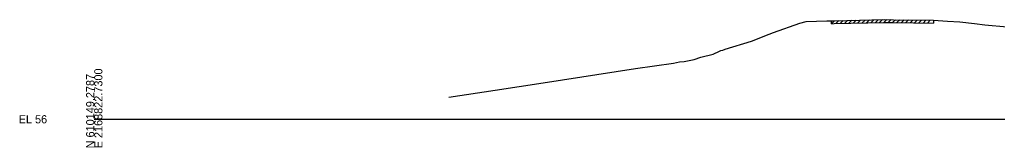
# Model space of a CAD drawing. Extents: x -26 to 6803, y -10 to 19606.
# Drawn here: x 1974.3 to 2310.6, y 12990.3 to 13034.3 of the extents above; entities that cross this region are included whole.
import ezdxf

# ---------------------------------------------------------------- set-up
doc = ezdxf.new("R2010")
doc.units = 0
for name, color, linetype in [('RD_GPK_XS_Cell', 7, 'Continuous'), ('RD_XS_ExGround', 7, 'Continuous'), ('RD_XS_ExPaveRet', 7, 'Continuous')]:
    doc.layers.add(name, color=color, linetype=linetype)

msp = doc.modelspace()

# ---------------------------------------------------------------- linework, layer by layer
at = {"layer": 'RD_GPK_XS_Cell'}
msp.add_line((2000, 13000), (2400, 13000), dxfattribs=at)
at = {"layer": 'RD_XS_ExGround'}
msp.add_lwpolyline([(2121.9, 13007.57), (2137.85, 13010.04), (2154.38, 13012.59), (2186.16, 13017.47), (2199.23, 13019.35), (2201.23, 13019.72), (2202.86, 13019.93), (2206.31, 13020.58), (2208.66, 13021.37), (2212.8, 13022.44), (2215.01, 13023.43), (2215.52, 13023.62), (2216.2, 13023.83), (2216.93, 13024.09), (2226.07, 13026.83), (2232.1, 13029.23), (2233.55, 13029.89), (2242.7, 13033.08), (2244.78, 13033.64), (2251.95, 13033.86), (2252.75, 13033.86), (2253.54, 13033.89), (2254.42, 13033.91), (2271.81, 13034.32), (2274.9, 13034.26), (2288.67, 13034.05), (2293.42, 13033.74), (2297.68, 13033.49), (2302.74, 13032.9), (2306.32, 13032.51), (2313.99, 13031.81)], dxfattribs=at)
at = {"layer": 'RD_XS_ExPaveRet'}
for p, q in [((2253.54, 13032.89), (2254.57, 13033.91)), ((2253.54, 13032.89), (2253.54, 13033.89)), ((2253.54, 13032.89), (2254.42, 13032.91)), ((2254.42, 13032.91), (2271.81, 13033.32)), ((2255.04, 13032.92), (2256.07, 13033.95)), ((2256.54, 13032.96), (2257.57, 13033.98)), ((2258.04, 13032.99), (2259.07, 13034.02)), ((2259.54, 13033.03), (2260.57, 13034.05)), ((2261.04, 13033.06), (2262.07, 13034.09)), ((2262.54, 13033.1), (2263.57, 13034.12)), ((2264.04, 13033.13), (2265.07, 13034.16)), ((2265.54, 13033.17), (2266.57, 13034.19)), ((2267.04, 13033.21), (2268.07, 13034.23)), ((2268.54, 13033.24), (2269.57, 13034.26)), ((2270.04, 13033.28), (2271.07, 13034.3)), ((2271.54, 13033.31), (2272.54, 13034.3)), ((2271.81, 13033.32), (2274.9, 13033.26)), ((2273.04, 13033.3), (2274.03, 13034.28)), ((2274.54, 13033.27), (2275.53, 13034.25)), ((2274.9, 13033.26), (2288.67, 13033.05)), ((2276.04, 13033.25), (2277.03, 13034.23)), ((2277.54, 13033.22), (2278.53, 13034.21)), ((2279.04, 13033.2), (2280.03, 13034.19)), ((2280.54, 13033.18), (2281.53, 13034.16)), ((2282.04, 13033.16), (2283.03, 13034.14)), ((2283.54, 13033.13), (2284.53, 13034.12)), ((2285.04, 13033.11), (2286.03, 13034.09)), ((2286.54, 13033.09), (2287.53, 13034.07)), ((2288.67, 13034.05), (2288.67, 13033.05)), ((2288.67, 13033.05), (2288.67, 13033.05))]:
    msp.add_line(p, q, dxfattribs=at)

# ---------------------------------------------------------------- texts
at = {"layer": 'RD_GPK_XS_Cell'}
for s, p in [('N 610149.2787', (2000, 12990)), ('E 2168822.7300', (2002.8, 12990))]:
    msp.add_text(s, height=2.8, rotation=90, dxfattribs=at).set_placement(p)
msp.add_text('EL 56', height=2.8, dxfattribs=at).set_placement((1974, 12998.6))

doc.saveas('drawing.dxf')
